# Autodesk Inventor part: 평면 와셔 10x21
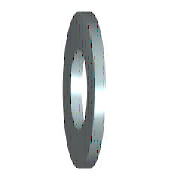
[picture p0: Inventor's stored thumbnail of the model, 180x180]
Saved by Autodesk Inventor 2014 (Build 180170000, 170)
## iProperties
IsCustomPart: 1
Created: 2012-02
Part Number: 평면 와셔 10x21
Material: 강철, 연강
Description: 평면 와셔
Document SubType Name: Modeling
Standard: KS B 1326
Designer: mduedu
Standards Organization: KS
Language: ko-KR
Size Designation: 10x21
Categories: <MemberInstance><Categories><Category DisplayName="조임쇠" InternalName="e4da775c-781d-43d5-af7c-5136215cf5a6" Mnemonic="FSTN"><Category DisplayName="와셔" InternalN
Density: 1 g/cm^3
Appearance: 노란색
Author: mduedu
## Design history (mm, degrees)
sketch "스케치"
  geometry: C1 r 10.5 at (0, 0); C2 r 5.25 at (0, 0); 1 further point
  constraints: 2 centre point, 2 coincident
  dimensions: "d0" = 10.5 diameter of C2 (= SD1); "d1" = 21 diameter of C1 (= SD2)
extrude "본체" new body sketch "스케치" distance "d2" = 2 (= SD); taper "d3" = 0 deg
workaxis "Work Axis1"
workplane "Work Plane1"
body "Solid1"
other parameters: "SD1" = 10.5 [user parameter; used in 1 equation term], "SD2" = 21 [user parameter; used in 1 equation term], "SD" = 2 [user parameter; used in 1 equation term], "d4" = 0, "d5" = 0, "d6" = 0, "d7" = 0
